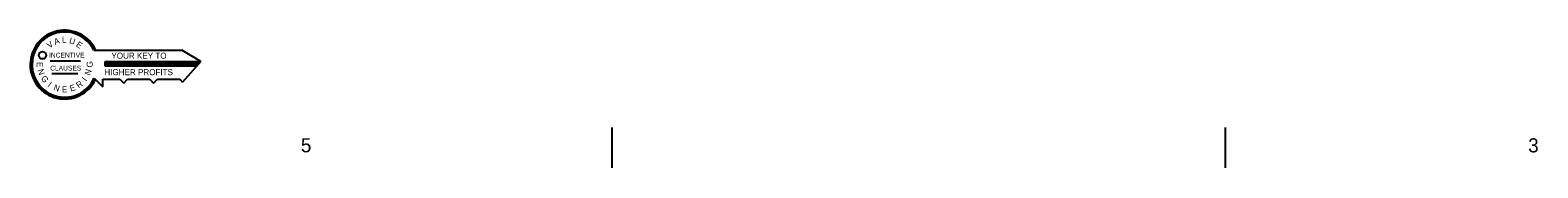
# Model space of a CAD drawing. Extents: x 0 to 320, y -4 to 473.
# Drawn here: x 20.361 to 21.923, y -4.171 to -4.029 of the extents above; entities that cross this region are included whole.
import ezdxf

# ---------------------------------------------------------------- set-up
doc = ezdxf.new("R2010")
doc.units = 0
doc.layers.add('Level 1', color=7, linetype='Continuous')

msp = doc.modelspace()

# ---------------------------------------------------------------- linework, layer by layer
at = {"layer": 'Level 1'}
for p, q in [((20.4273, -4.0499), (20.5184, -4.0499)), ((20.5383, -4.0616), (20.5184, -4.0499)), ((20.3823, -4.0608), (20.4135, -4.0608)), ((20.384, -4.074), (20.411, -4.074)), ((20.538, -4.0619), (20.4389, -4.0619)), ((20.4389, -4.0619), (20.4389, -4.0658)), ((20.537, -4.063), (20.4389, -4.063)), ((20.5362, -4.064), (20.4389, -4.064)), ((20.5352, -4.0651), (20.4389, -4.0651)), ((20.4389, -4.0658), (20.5345, -4.0658)), ((20.5383, -4.0616), (20.5193, -4.0828)), ((20.4278, -4.0786), (20.4368, -4.0877)), ((20.4368, -4.0877), (20.4368, -4.0799)), ((20.4368, -4.0799), (20.4544, -4.0799)), ((20.4544, -4.0799), (20.4583, -4.0838)), ((20.4583, -4.0838), (20.4622, -4.0799)), ((20.4622, -4.0799), (20.4854, -4.0799)), ((20.4854, -4.0799), (20.4893, -4.0838)), ((20.4893, -4.0838), (20.4932, -4.0799)), ((20.4932, -4.0799), (20.5164, -4.0799)), ((20.5164, -4.0799), (20.5193, -4.0828)), ((20.9636, -4.1298), (20.9636, -4.1714)), ((21.599, -4.1298), (21.599, -4.1714))]:
    msp.add_line(p, q, dxfattribs=at)
msp.add_circle((20.3743, -4.055), 0.00384, dxfattribs=at)
for radius, start, end in [(0.0356, 24.569, 334.4243), (0.0346, 25.3095, 334.4522), (0.0337, 26.0896, 335.5943)]:
    msp.add_arc((20.3971, -4.0647), radius, start, end, dxfattribs=at)

# ---------------------------------------------------------------- texts
for s, rotation, p in [('V', 35.9204, (20.3815, -4.0482)), ('A', 18.0731, (20.3873, -4.0442)), ('U', 342.1107, (20.4013, -4.0424)), ('E', 323.9298, (20.4084, -4.0452)), ('E', 270, (20.3683, -4.0619)), ('N', 288.0821, (20.369, -4.0704)), ('N', 71.9179, (20.4234, -4.0764)), ('G', 90, (20.4262, -4.0676)), ('G', 306.0537, (20.3722, -4.0789)), ('I', 323.5836, (20.3791, -4.0869)), ('N', 341.9179, (20.3852, -4.0908)), ('E', 18.2241, (20.4036, -4.0926)), ('R', 36.2206, (20.4118, -4.0894)), ('I', 53.5836, (20.4195, -4.0825))]:
    msp.add_text(s, height=0.00625, rotation=rotation, dxfattribs=at).set_placement(p)
for s, height, p in [('L', 0.00625, (20.3945, -4.0421)), ('INCENTIVE', 0.005, (20.381, -4.0574)), ('YOUR KEY TO', 0.00625, (20.4456, -4.0586)), ('CLAUSES', 0.005, (20.3822, -4.0708)), ('HIGHER PROFITS', 0.00625, (20.4383, -4.0756)), ('E', 0.00625, (20.3944, -4.0933)), ('5', 0.0146, (20.6418, -4.1554)), ('3', 0.0146, (21.9126, -4.1555))]:
    msp.add_text(s, height=height, dxfattribs=at).set_placement(p)

doc.saveas('drawing.dxf')
